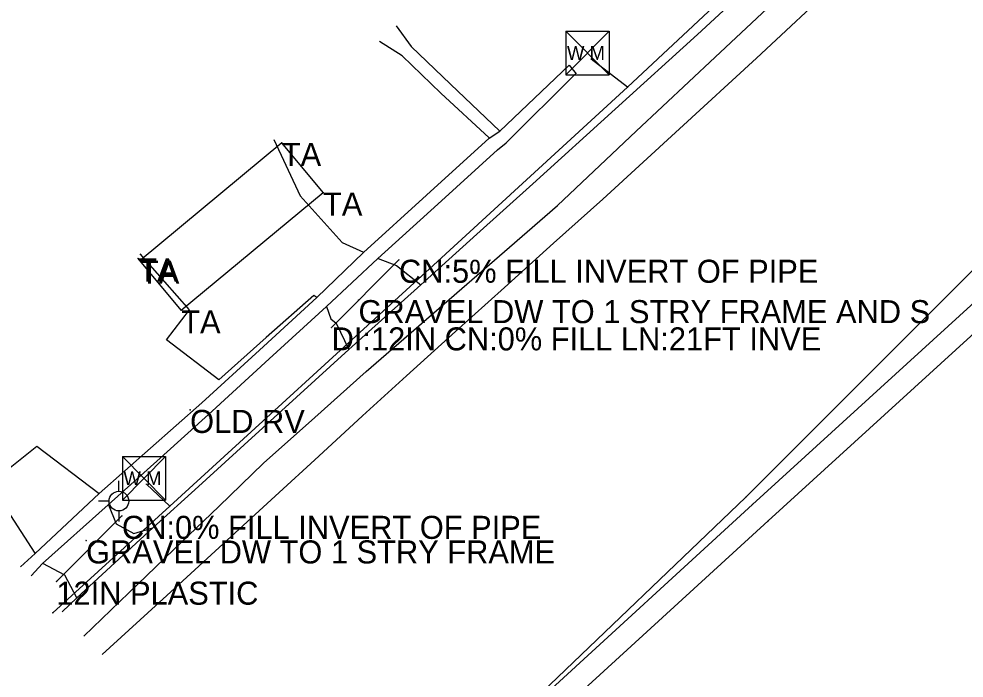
# Model space of a CAD drawing. Extents: x 1660112 to 1662239, y 668919 to 671377.
# Drawn here: x 1661239.8 to 1661444.9, y 669831.4 to 669974.4 of the extents above; entities that cross this region are included whole.
import ezdxf

# ---------------------------------------------------------------- set-up
doc = ezdxf.new("R2010")
doc.units = 0
for name, color, linetype in [('S_BUILDING', 7, 'Continuous'), ('S_BUILDING_ANNOT', 7, 'Continuous'), ('S_DRG_PT_SYM', 7, 'Continuous'), ('S_DRIVEWAY', 7, 'Continuous'), ('S_EDGE_PAVEMENT', 7, 'Continuous'), ('S_MSC_PT_SYM', 7, 'Continuous'), ('S_PAVEMENT_CROWN', 7, 'Continuous'), ('S_RAILROAD', 7, 'Continuous'), ('S_SIDE_DRAIN', 7, 'Continuous'), ('S_SIDE_DRAIN_ANNOT', 7, 'Continuous'), ('S_SIDEWALK', 7, 'Continuous'), ('S_STR_PT_SYM', 7, 'Continuous'), ('S_SURVEY_TEXT_ANNOT', 7, 'Continuous'), ('S_UTILITY_POLE', 7, 'Continuous'), ('S_UTL_PT_SYM', 7, 'Continuous'), ('S_WATER_UTILITIES', 7, 'Continuous')]:
    doc.layers.add(name, color=color, linetype=linetype)

msp = doc.modelspace()

# ---------------------------------------------------------------- linework, layer by layer
at = {"layer": 'S_BUILDING'}
for p, q in [((1661296.84, 669947.48), (1661266.07, 669921.94)), ((1661305.79, 669936.71), (1661296.84, 669947.48)), ((1661275.01, 669911.16), (1661305.79, 669936.71)), ((1661275.01, 669911.16), (1661265.68, 669922.4))]:
    msp.add_line(p, q, dxfattribs=at)
at = {"layer": 'S_DRG_PT_SYM'}
for points in [[(1661322.27, 669922.13), (1661322.27, 669922.18), (1661322.27, 669922.13), (1661322.22, 669922.13), (1661322.27, 669922.13), (1661322.27, 669922.08), (1661322.27, 669922.13), (1661322.32, 669922.13)], [(1661307.65, 669907.46), (1661307.65, 669907.51), (1661307.65, 669907.46), (1661307.6, 669907.46), (1661307.65, 669907.46), (1661307.65, 669907.41), (1661307.65, 669907.46), (1661307.7, 669907.46)], [(1661262.14, 669866.58), (1661262.14, 669866.63), (1661262.14, 669866.58), (1661262.09, 669866.58), (1661262.14, 669866.58), (1661262.14, 669866.53), (1661262.14, 669866.58), (1661262.19, 669866.58)], [(1661247.92, 669852.3), (1661247.92, 669852.35), (1661247.92, 669852.3), (1661247.87, 669852.3), (1661247.92, 669852.3), (1661247.92, 669852.25), (1661247.92, 669852.3), (1661247.97, 669852.3)]]:
    msp.add_lwpolyline(points, dxfattribs=at)
at = {"layer": 'S_DRIVEWAY'}
for points in [[(1661295.09, 669948.24), (1661300.83, 669935.96), (1661309.95, 669925.89), (1661314.56, 669923.74)], [(1661304.44, 669913.97), (1661303.77, 669914.39), (1661293.48, 669905.23), (1661283.2, 669896.08), (1661271.82, 669904.73), (1661276.83, 669911.29), (1661266.12, 669923.38)], [(1661317.76, 669922.38), (1661321.72, 669920.86), (1661327.02, 669916.7)], [(1661306.52, 669911.99), (1661307.49, 669909.28), (1661308.66, 669908.39), (1661311.42, 669902.66)], [(1661243.33, 669858.48), (1661233.44, 669873.57), (1661243.64, 669881.7), (1661257.23, 669871.4)], [(1661259.2, 669868.97), (1661260.91, 669864.86), (1661264.76, 669862.72), (1661268.87, 669863.99)], [(1661252.39, 669848.76), (1661249.72, 669853.7), (1661244.99, 669856.24)]]:
    msp.add_lwpolyline(points, dxfattribs=at)
at = {"layer": 'S_EDGE_PAVEMENT'}
for points in [[(1661249.19, 669845.77), (1661252.39, 669848.76), (1661268.86, 669863.99), (1661278.76, 669872.97), (1661288.66, 669881.95), (1661300.04, 669892.31), (1661311.42, 669902.66), (1661327.02, 669916.7), (1661339.16, 669927.65), (1661351.29, 669938.61), (1661369.17, 669954.79), (1661387.06, 669970.96), (1661398.2, 669981.35), (1661409.34, 669991.75), (1661421.08, 670002.53), (1661432.82, 670013.32), (1661449.38, 670028.66), (1661451.32, 670030.24), (1661455.87, 670040.73), (1661454.57, 670045.91), (1661454.4, 670049.73)], [(1661484.97, 670015.57), (1661481.44, 670017.1), (1661474.37, 670019.33), (1661466.03, 670019.66), (1661456.43, 670012.6), (1661444.31, 670002.59), (1661432.19, 669992.58), (1661429.76, 669993.52), (1661418.03, 669982.83), (1661399.88, 669965.82), (1661383.18, 669950.54), (1661366.48, 669935.26), (1661355.84, 669925.69), (1661345.19, 669916.12), (1661334.54, 669906.55), (1661323.9, 669896.98), (1661314.39, 669888.26), (1661304.88, 669879.54), (1661295.37, 669870.82), (1661285.87, 669862.1), (1661271.87, 669849.3), (1661257.87, 669836.51)]]:
    msp.add_lwpolyline(points, dxfattribs=at)
at = {"layer": 'S_MSC_PT_SYM'}
for points in [[(1661313.48, 669913.37), (1661313.48, 669913.42), (1661313.48, 669913.37), (1661313.43, 669913.37), (1661313.48, 669913.37), (1661313.48, 669913.32), (1661313.48, 669913.37), (1661313.53, 669913.37)], [(1661276.94, 669889.56), (1661276.94, 669889.61), (1661276.94, 669889.56), (1661276.89, 669889.56), (1661276.94, 669889.56), (1661276.94, 669889.51), (1661276.94, 669889.56), (1661276.99, 669889.56)], [(1661397.52, 669870.6), (1661397.52, 669870.65), (1661397.52, 669870.6), (1661397.47, 669870.6), (1661397.52, 669870.6), (1661397.52, 669870.55), (1661397.52, 669870.6), (1661397.57, 669870.6)], [(1661398.98, 669869.07), (1661398.98, 669869.12), (1661398.98, 669869.07), (1661398.93, 669869.07), (1661398.98, 669869.07), (1661398.98, 669869.02), (1661398.98, 669869.07), (1661399.03, 669869.07)], [(1661402.43, 669865.48), (1661402.43, 669865.53), (1661402.43, 669865.48), (1661402.38, 669865.48), (1661402.43, 669865.48), (1661402.43, 669865.43), (1661402.43, 669865.48), (1661402.48, 669865.48)], [(1661254.37, 669861.25), (1661254.37, 669861.3), (1661254.37, 669861.25), (1661254.32, 669861.25), (1661254.37, 669861.25), (1661254.37, 669861.2), (1661254.37, 669861.25), (1661254.42, 669861.25)]]:
    msp.add_lwpolyline(points, dxfattribs=at)
at = {"layer": 'S_PAVEMENT_CROWN'}
msp.add_lwpolyline([(1661253.85, 669840.46), (1661263.61, 669849.85), (1661273.37, 669859.23), (1661283.14, 669868.61), (1661292.9, 669878), (1661304.03, 669887.93), (1661315.16, 669897.86), (1661325.53, 669906.87), (1661335.91, 669915.88), (1661346.29, 669924.88), (1661356.66, 669933.89), (1661373.78, 669949.99), (1661390.9, 669966.09), (1661402.21, 669976.63), (1661413.52, 669987.17), (1661425.13, 669997.67), (1661436.73, 670008.16), (1661454.08, 670023.57), (1661444.42, 670014.94), (1661434.75, 670006.32), (1661450.56, 670020.53), (1661466.37, 670034.74)], dxfattribs=at)
at = {"layer": 'S_RAILROAD'}
for p, q in [((1661397.52, 669870.6), (1661448.04, 669921.07)), ((1661398.98, 669869.07), (1661451.97, 669917.34)), ((1661402.43, 669865.48), (1661455.22, 669913.63)), ((1661334.95, 669810.8), (1661397.52, 669870.6)), ((1661335.82, 669811.18), (1661398.98, 669869.07)), ((1661338.9, 669807.53), (1661402.43, 669865.48))]:
    msp.add_line(p, q, dxfattribs=at)
at = {"layer": 'S_SIDE_DRAIN'}
for p, q in [((1661307.65, 669907.46), (1661322.27, 669922.13)), ((1661247.92, 669852.3), (1661262.14, 669866.58))]:
    msp.add_line(p, q, dxfattribs=at)
at = {"layer": 'S_SIDEWALK'}
for points in [[(1661321.68, 669972.85), (1661324.89, 669968.38), (1661333.45, 669960.24), (1661344.15, 669950.01)], [(1661341.84, 669948.55), (1661331.36, 669958.28), (1661322.98, 669966.37), (1661318.03, 669969.45)], [(1661240.13, 669855.54), (1661243.3, 669858.43), (1661257.23, 669871.4), (1661268.37, 669881.24), (1661279.52, 669891.08), (1661292, 669902.52), (1661304.47, 669913.96), (1661314.57, 669923.73), (1661328.21, 669936.13), (1661341.84, 669948.53), (1661344.15, 669950), (1661359.19, 669964.33), (1661360.75, 669962.46)], [(1661242.46, 669853.59), (1661244.91, 669856.24), (1661259.13, 669868.97), (1661270.42, 669879.12), (1661281.71, 669889.26), (1661294.12, 669900.64), (1661306.53, 669912.02), (1661317.71, 669922.4), (1661330.68, 669934.19), (1661343.64, 669945.98), (1661345.57, 669947.5), (1661360.69, 669962.51)]]:
    msp.add_lwpolyline(points, dxfattribs=at)
at = {"layer": 'S_STR_PT_SYM'}
for points in [[(1661296.84, 669947.48), (1661296.84, 669947.53), (1661296.84, 669947.48), (1661296.79, 669947.48), (1661296.84, 669947.48), (1661296.84, 669947.43), (1661296.84, 669947.48), (1661296.89, 669947.48)], [(1661305.79, 669936.71), (1661305.79, 669936.76), (1661305.79, 669936.71), (1661305.74, 669936.71), (1661305.79, 669936.71), (1661305.79, 669936.66), (1661305.79, 669936.71), (1661305.84, 669936.71)], [(1661265.68, 669922.4), (1661265.68, 669922.45), (1661265.68, 669922.4), (1661265.63, 669922.4), (1661265.68, 669922.4), (1661265.68, 669922.35), (1661265.68, 669922.4), (1661265.73, 669922.4)], [(1661266.07, 669921.94), (1661266.07, 669921.99), (1661266.07, 669921.94), (1661266.02, 669921.94), (1661266.07, 669921.94), (1661266.07, 669921.89), (1661266.07, 669921.94), (1661266.12, 669921.94)], [(1661275.01, 669911.16), (1661275.01, 669911.21), (1661275.01, 669911.16), (1661274.96, 669911.16), (1661275.01, 669911.16), (1661275.01, 669911.11), (1661275.01, 669911.16), (1661275.06, 669911.16)]]:
    msp.add_lwpolyline(points, dxfattribs=at)
at = {"layer": 'S_UTILITY_POLE'}
for p, q in [((1661261.47, 669871.89), (1661261.47, 669874.14)), ((1661259.38, 669869.76), (1661257.06, 669869.76)), ((1661261.55, 669865.34), (1661261.55, 669867.66))]:
    msp.add_line(p, q, dxfattribs=at)
msp.add_circle((1661261.48, 669869.78), 2.13, dxfattribs=at)
at = {"layer": 'S_UTL_PT_SYM'}
for points in [[(1661364.01, 669965.65), (1661364.01, 669965.7), (1661364.01, 669965.65), (1661363.96, 669965.65), (1661364.01, 669965.65), (1661364.01, 669965.6), (1661364.01, 669965.65), (1661364.06, 669965.65)], [(1661371.87, 669959.59), (1661371.87, 669959.64), (1661371.87, 669959.59), (1661371.82, 669959.59), (1661371.87, 669959.59), (1661371.87, 669959.54), (1661371.87, 669959.59), (1661371.92, 669959.59)], [(1661371.9, 669959.56), (1661371.9, 669959.61), (1661371.9, 669959.56), (1661371.85, 669959.56), (1661371.9, 669959.56), (1661371.9, 669959.51), (1661371.9, 669959.56), (1661371.95, 669959.56)], [(1661328.86, 669920.15), (1661328.86, 669920.2), (1661328.86, 669920.15), (1661328.81, 669920.15), (1661328.86, 669920.15), (1661328.86, 669920.1), (1661328.86, 669920.15), (1661328.91, 669920.15)], [(1661267.5, 669873.45), (1661267.5, 669873.5), (1661267.5, 669873.45), (1661267.45, 669873.45), (1661267.5, 669873.45), (1661267.5, 669873.4), (1661267.5, 669873.45), (1661267.55, 669873.45)], [(1661272.56, 669868.71), (1661272.56, 669868.76), (1661272.56, 669868.71), (1661272.51, 669868.71), (1661272.56, 669868.71), (1661272.56, 669868.66), (1661272.56, 669868.71), (1661272.61, 669868.71)], [(1661272.57, 669868.7), (1661272.57, 669868.75), (1661272.57, 669868.7), (1661272.52, 669868.7), (1661272.57, 669868.7), (1661272.57, 669868.65), (1661272.57, 669868.7), (1661272.62, 669868.7)], [(1661247.14, 669845.57), (1661247.14, 669845.62), (1661247.14, 669845.57), (1661247.09, 669845.57), (1661247.14, 669845.57), (1661247.14, 669845.52), (1661247.14, 669845.57), (1661247.19, 669845.57)]]:
    msp.add_lwpolyline(points, dxfattribs=at)
at = {"layer": 'S_WATER_UTILITIES'}
for p, q in [((1661371.87, 669959.59), (1661408.52, 669993.88)), ((1661358.52, 669971.72), (1661367.86, 669971.72)), ((1661358.52, 669971.72), (1661358.52, 669962.23)), ((1661358.52, 669971.72), (1661367.86, 669962.23)), ((1661367.86, 669971.72), (1661358.52, 669962.23)), ((1661367.86, 669971.72), (1661367.86, 669962.23)), ((1661371.9, 669959.56), (1661364.01, 669965.65)), ((1661358.52, 669962.23), (1661367.86, 669962.23)), ((1661328.86, 669920.15), (1661371.87, 669959.59)), ((1661272.57, 669868.7), (1661328.86, 669920.15)), ((1661262.26, 669879.46), (1661271.6, 669879.46)), ((1661262.26, 669879.46), (1661262.26, 669869.97)), ((1661262.26, 669879.46), (1661271.6, 669869.97)), ((1661271.6, 669879.46), (1661262.26, 669869.97)), ((1661271.6, 669879.46), (1661271.6, 669869.97)), ((1661272.56, 669868.71), (1661267.5, 669873.45)), ((1661262.26, 669869.97), (1661271.6, 669869.97)), ((1661247.14, 669845.57), (1661272.57, 669868.7))]:
    msp.add_line(p, q, dxfattribs=at)

# ---------------------------------------------------------------- texts
at = {"layer": 'S_BUILDING_ANNOT'}
for p in [(1661296.84, 669942.48), (1661305.79, 669931.71), (1661265.68, 669917.4), (1661266.07, 669916.94), (1661275.01, 669906.16)]:
    msp.add_text('TA', height=5, dxfattribs=at).set_placement(p)
at = {"layer": 'S_SIDE_DRAIN_ANNOT'}
for s, p in [('CN:5% FILL INVERT OF PIPE', (1661322.27, 669917.13)), ('DI:12IN CN:0% FILL LN:21FT INVE', (1661307.65, 669902.46)), ('CN:0% FILL INVERT OF PIPE', (1661262.14, 669861.58)), ('12IN PLASTIC', (1661247.92, 669847.3))]:
    msp.add_text(s, height=5, dxfattribs=at).set_placement(p)
at = {"layer": 'S_SURVEY_TEXT_ANNOT'}
for s, p in [('GRAVEL DW TO 1 STRY FRAME AND S', (1661313.48, 669908.37)), ('OLD RV', (1661276.94, 669884.56)), ('GRAVEL DW TO 1 STRY FRAME', (1661254.37, 669856.25))]:
    msp.add_text(s, height=5, dxfattribs=at).set_placement(p)
at = {"layer": 'S_WATER_UTILITIES'}
for p in [(1661358.73, 669965.49), (1661262.47, 669873.23)]:
    msp.add_text('W M', height=3, rotation=360, dxfattribs=at).set_placement(p)

doc.saveas('drawing.dxf')
